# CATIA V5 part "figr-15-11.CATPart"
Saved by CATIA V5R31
Part number: Part1
Bounding box of the stored display mesh (mm): x -50 to 50, y -32.5 to 33.5, z -52 to 1
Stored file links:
  D:\PROJECTS\Project 2021\US EDITION\CATIA V5 6R 2021\Resources\Part Files\c15_catia_v5_6r2021_prt\figr-15-11.CATPart
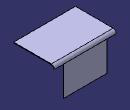
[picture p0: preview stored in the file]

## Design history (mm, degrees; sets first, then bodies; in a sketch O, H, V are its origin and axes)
SheetMetalParameters1: Thickness 1, BendRadius 4, KFactor 0.475772 {= log(min(100,max(20*SheetMetalParameters1.BendRadius,SheetMetalParameters1.Thickness)/SheetMetalParameters1.Thickness))/log(100)/2}, ReliefRadialLength 4, ReliefAxialLength 4, MinimumBendRadius 0
Body1 (main body)
  Sketch1 on xy-plane, origin (0, 0, 0), H (1, 0, 0), V (0, 1, 0)
    line L1 (-50, 32.5) -> (50, 32.5)
    line L2 (50, 32.5) -> (50, -32.5)
    line L3 (50, -32.5) -> (-50, -32.5)
    line L4 (-50, -32.5) -> (-50, 32.5)
    length L1 = 100
    length L2 = 65
    horizontal: L1 H, L3 H
    vertical: L2 V, L4 V
    symmetry: L4 L2 V, L1 L3 H
  Wall1: Thickness 1, Profile Sketch1
  d_NewWallOnEdge1: NewWallOnEdge_Edge edge [face of Wall1 | face of Wall1], NewWallOnEdge_Length 53, NewWallOnEdge_HeightLimitOffset 0, NewWallOnEdge_WidthOffset1 -15, NewWallOnEdge_WidthOffset2 -15, NewWallOnEdge_Angle 90, NewWallOnEdge_BendRadiusValue 4 {= SheetMetalParameters1.BendRadius}, NewWallOnEdge_BendTable SheetMetalParameters1, KFacteur 0.475772 {= log(min(100,max(20*d_NewWallOnEdge1.Radius,SheetMetalParameters1.Thickness)/SheetMetalParameters1.Thickness))/log(100)/2}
